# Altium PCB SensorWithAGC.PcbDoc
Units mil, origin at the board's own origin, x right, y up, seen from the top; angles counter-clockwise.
Board outline 6000 x 4000 mil, 2 copper layers (Top Layer, Bottom Layer); 30 components, 19 nets, 80 pads, 13 vias.
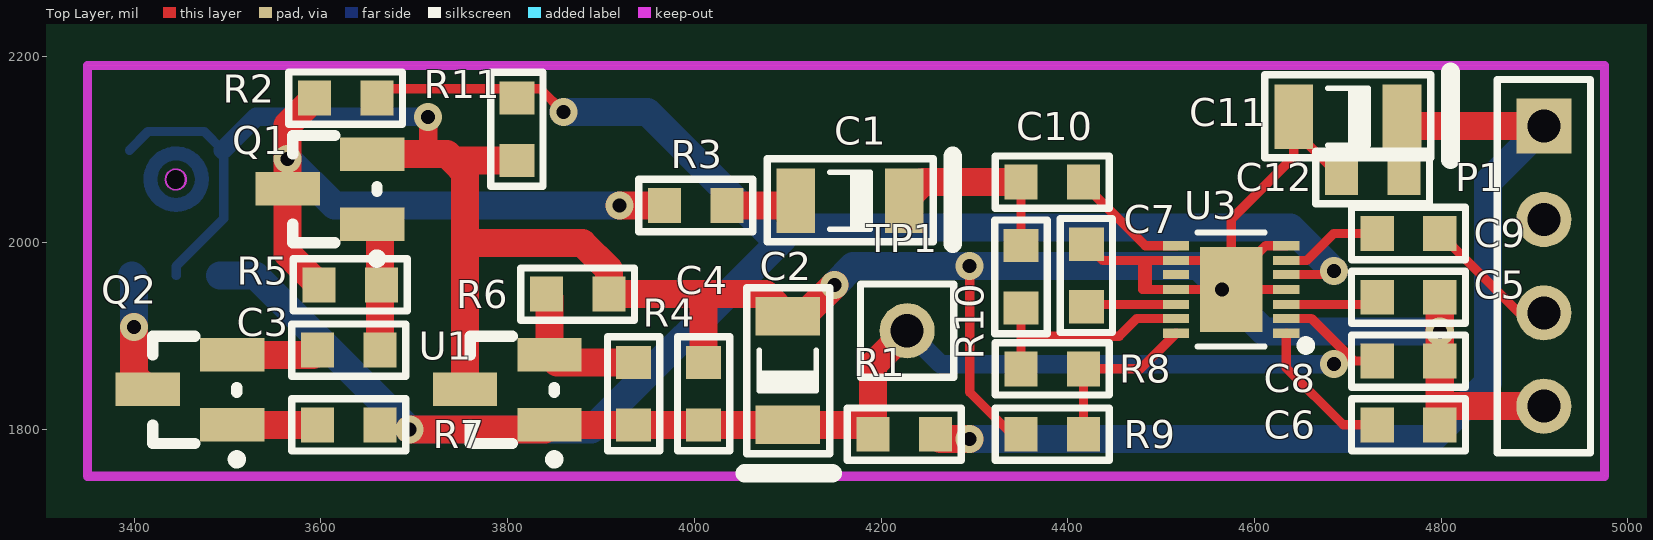
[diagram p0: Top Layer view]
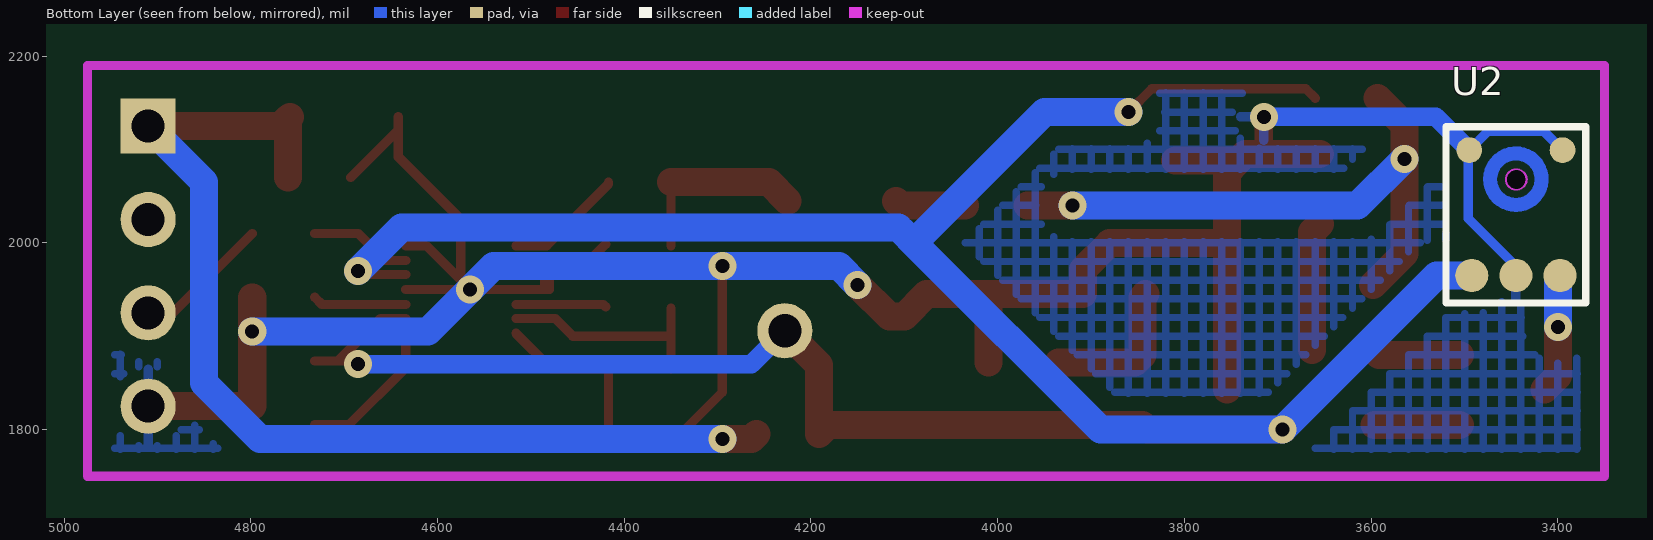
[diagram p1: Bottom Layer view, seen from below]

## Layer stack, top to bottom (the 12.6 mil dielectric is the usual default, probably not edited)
Top Solder: solder mask 0.4, Solder Resist, Dk 3.5
Top Layer: signal copper 1.4
Dielectric 1: dielectric 12.6, FR-4, Dk 4.8
Bottom Layer: signal copper 1.4
Bottom Solder: solder mask 0.4, Solder Resist, Dk 3.5

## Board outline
1000,1000 7000,1000 7000,5000 1000,5000
cut-out: 3445,2056.95 cw(c3445,2067.98) 3433.98,2067.98 cw(c3445,2067.98) 3445,2079 cw(c3445,2067.98) 3456.02,2067.98 cw(c3445,2067.98)
cut-out: 3444,2056.95 ccw(c3444,2067.98) 3455.02,2067.98 ccw(c3444,2067.98) 3444,2079 ccw(c3444,2067.98) 3432.98,2067.98 ccw(c3444,2067.98)

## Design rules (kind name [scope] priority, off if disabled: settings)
Clearance [All] p1: gap=20
PolygonConnect [All] p1: connectstyle=Relief reliefconductorwidth=10 reliefentries=4 polygonreliefangle="90 Angle" airgapwidth=10
RoutingVias [All] p1: holewidth=28 width=50 viastyle="Through Hole" minholewidth=15 minwidth=10 maxholewidth=50 maxwidth=50
SolderMaskExpansion [All] p1: expansion=4
Width [All] p1: maxlimit=100 minlimit=10 preferedwidth=10
30 further rules are at their usual default settings.

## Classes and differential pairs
component class SensorWithAGC: C1 C2 C3 C4 C5 C6 C7 C8 C9 C10 P1 Q1 Q2 R1 R2 R3 R4 R5 R6 R7 R8 R9 R10 TP1 U1 U2 U3

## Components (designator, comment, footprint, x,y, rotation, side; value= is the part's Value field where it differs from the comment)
C1 "1uF/1206" TAN_A 4166.93,2045 r0 top
C2 "1uF/1206" TAN_A 4100,1863.07 r270 top
C3 "0.1uF/0603" C0603 3630,1885 r0 top
C4 "0.1uF/0603" C0603 4010,1838.46 r270 top
C5 "2.2uF/0603" C0603 4765,1941.67 r180 top
C6 "47nF/0603" C0603 4765,1805 r180 top
C7 "0.47uF/0603" C0603 4420,1965 r270 top
C8 "1uF/0603" C0603 4765,1873.33 r180 top
C9 "1uF/0603" C0603 4765,2010 r180 top
C10 "0.1uF/0603" C0603 4383.46,2065 r180 top
C11 "1uF/1206" TAN_A 4700,2135 r0 top (schematic designator C1)
C12 "0.1uF/0603" C0603 4726.54,2070 r180 top (schematic designator C10)
P1 "Header 4" HDR1X4 4910,2125 r270 top
Q1 "MMBT3904" SOT-23 3609.72,2057.5 r90 top
Q2 "MMBT3904" SOT-23 3459.72,1842.5 r90 top
R1 "100ohm/0805" R0603 4225,1795 r0 top
R2 "10K/0603" R0603 3626.54,2155 r180 top
R3 "0 ohm/0603" R0603 4001.54,2040 r180 top
R4 "10K/1%/0603" R0603 3935,1838.46 r90 top
R5 "220K/0603" R0603 3631.54,1955 r0 top
R6 "51K/1%/0603" R0603 3875,1945 r0 top
R7 "20K/0603" R0603 3630,1805 r0 top
R8 "150K/1%/0603" R0603 4383.46,1865 r0 top
R9 "100K/1%/0603" R0603 4383.46,1795 r180 top
R10 "2.2K/1%/0603" R0603 4350,1963.46 r90 top
R11 "0 ohm/0603" R0603 3810,2121.54 r270 top (schematic designator R3)
TP1 "REF" TP 4230,1905 r0 top
U1 "TL431BCDBZR" SOT-23 3799.72,1842.5 r90 top
U2 "INMP411" INMP411 3397.76,1965 r270 bottom
U3 "MAX9814" DFN300X300X80-15N 4575,1950 r180 top

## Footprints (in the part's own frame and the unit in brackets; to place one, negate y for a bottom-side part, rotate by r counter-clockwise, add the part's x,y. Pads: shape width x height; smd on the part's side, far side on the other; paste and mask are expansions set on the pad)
C0603 [mm]
  rect 0.9x0.95 smd: 1(0.85,0) 2(-0.85,0)
  silkscreen extent -1.55,-0.71 1.55,0.71, body extent -0.85,-0.45 0.85,0.45, height 0.45
DFN300X300X80-15N [mil]
  rect 28x10 smd: 1(-59,47) 2(-59,31) 3(-59,16) 4(-59,0) 5(-59,-16) 6(-59,-31) 7(-59,-47) 8(59,-47) 9(59,-31) 10(59,-16) 11(59,0) 12(59,16) 13(59,31) 14(59,47)
  rect 67x91 smd: 15(0,0)
  silkscreen extent -36,-61 36,61
HDR1X4 [mm] "Connector; Header; 4 Position"
  rect 1.5x1.5 hole 0.9: 1(0,0)
  round 1.5 hole 0.9: 2(2.54,0) 3(5.08,0) 4(7.62,0)
  silkscreen extent -1.27,-1.27 8.89,1.27
INMP411 [mm]
  round 0.9 smd: 1(0,0) 5(0,-2.4) 6(0,-1.2)
  round 0.7 smd mask+0.09: 2(-3.41,0.07)
  round 0.7 smd mask+0.08: 4(-3.41,-2.47)
  Top Layer lines w0.381: -1.92,-1.2 ccw(c-2.62,-1.2) -2.62,-1.9 ccw(c-2.62,-1.2) -1.92,-1.2
  silkscreen extent -4.05,-3.1 0.75,0.7
R0603 [mm]
  rect 0.9x0.95 smd: 1(0.85,0) 2(-0.85,0)
  silkscreen extent -1.55,-0.71 1.55,0.71, body extent -0.85,-0.45 0.85,0.45, height 0.45
SOT-23 [mil]
  rect 36x68.9 smd: 1(-37.5,-45.28) 2(37.5,-45.28) 3(0.5,45.28)
  silkscreen extent -79,-55 58,40, body extent -58,-35 60,20, height 47
TAN_A [mm]
  rect 1.05x1.75 smd: 1(1.475,0) 2(-1.475,0)
  silkscreen extent -2.26,-1.17 2.79,1.22, body extent -1.6,-0.85 1.6,0.85, height 0.55
TP [mm]
  round 1.5 hole 0.9: 1(-0.05,0.021)
  silkscreen extent -1.32,-1.25 1.22,1.29

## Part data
C1 C2 C3 C4 C5 C6 C7 C8 C9 C10 C11 C12: library part C
P1: "Header, 4-Pin"
Q1 Q2: "NPN Transistor"
R1 R2 R3 R4 R5 R6 R7 R8 R9 R10 R11: library part RES
TP1: library part Testpoint
U1: library part TL431CDBZR, "CAN NOT BE MFDT or MSDT"

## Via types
v1: diameter 30, hole 15, Top Layer to Bottom Layer, 13 vias

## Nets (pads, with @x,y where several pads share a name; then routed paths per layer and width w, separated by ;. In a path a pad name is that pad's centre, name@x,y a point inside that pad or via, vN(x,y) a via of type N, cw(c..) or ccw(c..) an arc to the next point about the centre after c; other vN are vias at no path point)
5V: C11.1 C12.2 P1.1 R1.1 | length 1147.5
  Top Layer w30: R1.1 4263.46,1790 v1(4295,1790) ; C11.1 C11.1@4760,2133.07 ; C12.2 C11.1@4760,2133.07 ; P1.1 4768.07,2125 C11.1@4760,2133.07
  Bottom Layer w30: v1(4295,1790) 4790,1790 4850,1850 4850,2065 P1.1 P1.1@4910,2115
GND: C2.2 C4.2 C5.2 C6.2 C7.2 C8.2 C11.2 C12.1 P1.4 Q1.2 R6.1 R9.1 R11.1 U1.3 U2.2 U2.4 U2.6 U3.4 U3.7 U3.9 U3.11 U3.15 | length 3277.8
  Top Layer w10: v1(4295,1975) 4295,1840 4340,1795 R9.1 ; C7.2 4437.46,1981 U3.9 4544,1981 U3.15 U3.4 ; 4480,1950 U3.11 v1(4565,1950) ; U3.7 4612,1997 4575,1960 4575,2025 4641.93,2091.93 C11.2@4641.93,2121.14 ; C11.2 C11.2@4641.93,2121.14 ; C12.1 C11.2@4641.93,2121.14
  Top Layer w20: 3715,2095 v1(3715,2135)
  Top Layer w30: Q1.2 3715,2095 3735,2095 3741.93,2088.07 ; U1.3 3754.45,2000 ; R11.1 3741.93,2088.07 ; C4.2 4010,1945 ; v1(4150,1955) 4116.14,1921.14 C2.2 4076.14,1945 4010,1945 ; C5.2 v1(4798.46,1905) C8.2 4798.46,1825 P1.4 ; 3741.93,2088.07 3754.45,2075.55 3754.45,2000 ; 3754.45,2000 3880,2000 3908.46,1971.54 R6.1 4010,1945
  Bottom Layer w10: U2.2 3414.94,2119.19 3475.06,2119.19 U2.4 3496.04,2099.25 3496.04,2026.04 3445,1975 U2.6
  Bottom Layer w20: U2.4 3530.75,2135 v1(3715,2135)
  Bottom Layer w30: v1(4150,1955) 4170,1975 v1(4295,1975) 4540,1975 v1(4565,1950) 4610,1905 v1(4798.46,1905)
L1AMP: C1.1 C10.1 R10.1 | length 201.4
  Top Layer w10: R10.1 C10.1
  Top Layer w30: C1.1 4245,2065 C10.1
MICBIAS2: R8.2 R10.2 U3.13 | length 239.9
  Top Layer w10: R8.2 4350,1897.5 ; R10.2 4350,1897.5 ; U3.13 4474,1919 4455,1900 4352.5,1900 4350,1897.5
MICIN: C9.2 P1.3 | length 146.7
  Top Layer w10: C9.2 4883.46,1925 P1.3
NetC1_2: C1.2 R3.2 | length 75.9
  Top Layer w30: R3.2 4103.86,2040 C1.2
NetC3_1: C3.1 Q1.1 R5.1 | length 138.5
  Top Layer w30: Q1.1 3663.46,2011.54 C3.1
NetC3_2: C3.2 Q2.2 | length 93.6
  Top Layer w30: Q2.2 3591.54,1880 C3.2
NetC5_1: C5.1 U3.3 | length 100.7
  Top Layer w10: U3.3 4723.87,1934 C5.1
NetC6_1: C6.1 U3.1 | length 159.8
  Top Layer w10: U3.1 4634,1866 4695,1805 C6.1
NetC7_1: C7.1 U3.12 | length 97
  Top Layer w10: C7.1 4422.46,1934 U3.12
NetC9_1: C9.1 U3.6 | length 109.5
  Top Layer w10: U3.6 4656,1981 4685,2010 C9.1
NetC10_2: C10.2 U3.8 | length 128.4
  Top Layer w10: C10.2 4416.93,2063.07 4483,1997 U3.8
NetQ1_3: Q1.3 R2.1 R3.1 R5.2 | length 650.1
  Top Layer w30: R2.1 3564.45,2126.38 v1(3564.45,2090) Q1.3 3564.45,1988.62 R5.2 ; v1(3920,2040) R3.1
  Bottom Layer w30: v1(3564.45,2090) 3614.45,2040 v1(3920,2040)
NetQ2_1: Q2.1 R7.2 | length 91.5
  Top Layer w30: Q2.1 R7.2
NetQ2_3: Q2.3 U2.1 | length 128.9
  Top Layer w30: v1(3400,1910) 3400,1857.45 Q2.3
  Bottom Layer w30: U2.1 3400,1962.76 v1(3400,1910)
NetR4_1: R4.1 R6.2 U1.2 | length 159.8
  Top Layer w30: R6.2 3845,1941.54 U1.2 3853.07,1871.93 R4.1
NetR8_1: R8.1 R9.2 U3.14 | length 184.8
  Top Layer w10: R9.2 R8.1 4478,1865 U3.14
REF: C2.1 C4.1 C8.1 R1.2 R2.2 R4.2 R7.1 R11.2 TP1.1 U1.1 U2.5 U3.2 U3.5 | length 3165
  Top Layer w10: R2.2 3670,2165 3835,2165 v1(3860,2140) ; U3.2 4661,1919 4706.67,1873.33 ; U3.5 4681,1966 v1(4685,1970) ; v1(4685,1870) 4688.33,1873.33 4706.67,1873.33 ; C8.1 4706.67,1873.33
  Top Layer w30: v1(3695,1800) 3840,1800 U1.1 R4.2 C4.1 C2.1 4181.54,1805 R1.2 4191.54,1869.35 TP1.1
  Bottom Layer w10: 4102.5,2012.5 4106.25,2016.25
  Bottom Layer w20: TP1.1 4263.86,1870 v1(4685,1870)
  Bottom Layer w30: U2.5 3530,1965 v1(3695,1800) 3890,1800 4090,2000 ; v1(3860,2140) 3950,2140 4090,2000 ; 4102.5,2012.5 4090,2000 ; 4106.25,2016.25 4638.75,2016.25 v1(4685,1970)
pads on no net: P1.2 U3.10

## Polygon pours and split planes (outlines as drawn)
GND on Top Layer "Keep-Out Layer-No Net" (hatched 90Degree grid 20 track 8, remove dead copper, pour order 0): 3350,2190 4975,2190 4975,1750 3350,1750
GND on Bottom Layer "Keep-Out Layer-No Net" (hatched 90Degree grid 20 track 8, remove dead copper, pour order 2): 3350,2190 4975,2190 4975,1750 3350,1750

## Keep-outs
Keep-Out Layer:
  circle w1.97: c3444.78,2067.82 r11.02
  lines w10: 3350,1750 3350,2190 4975,2190 4975,1750 3350,1750

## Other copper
Top Layer:
  rectangle net GND: 4475,1950 4490,1980

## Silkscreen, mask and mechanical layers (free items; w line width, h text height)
Top Overlay:
  circle w10: c4655,1890 r5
